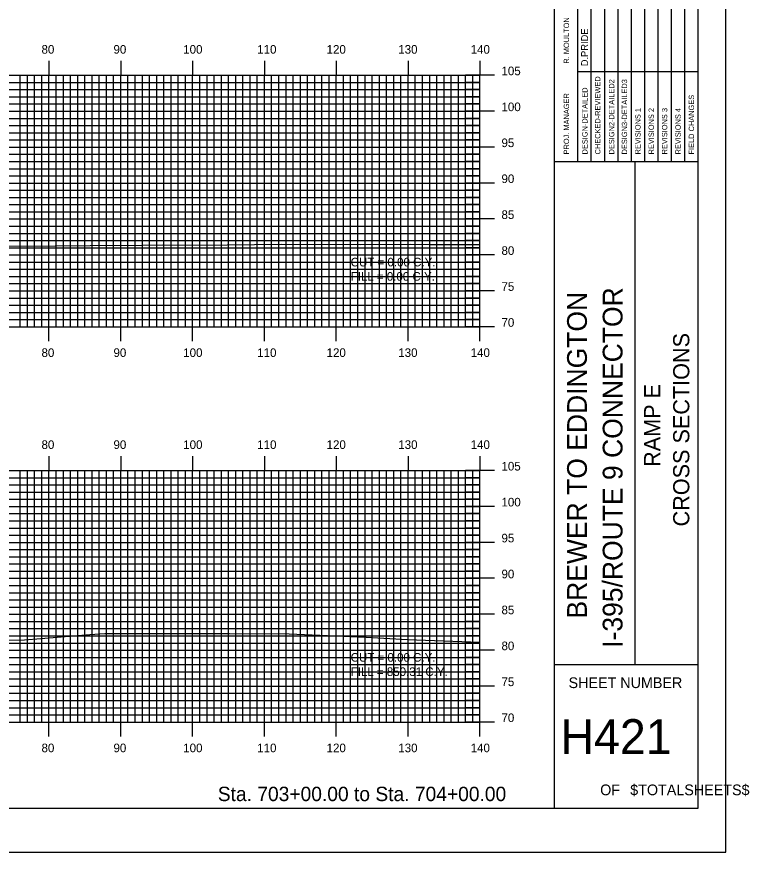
# Model space of a CAD drawing. Extents: x 853329 to 853673, y 364366 to 364586.
# Drawn here: x 853570.7 to 853672.7, y 364365.7 to 364481.9 of the extents above; entities that cross this region are included whole.
import ezdxf

# ---------------------------------------------------------------- set-up
doc = ezdxf.new("R2010")
doc.units = 0
for name, color, linetype in [('BORDER', 7, 'Continuous'), ('D_Text_Standard', 7, 'Continuous'), ('H_V ANNOTATION', 7, 'Continuous'), ('MAJOR', 7, 'Continuous'), ('MINOR', 7, 'Continuous'), ('PLOT BOUNDARY', 7, 'Continuous'), ('S_Roadway_Centerline', 7, 'Continuous')]:
    doc.layers.add(name, color=color, linetype=linetype)

msp = doc.modelspace()

# ---------------------------------------------------------------- linework, layer by layer
at = {"layer": 'BORDER'}
for p, q in [((853645.6, 364371.79), (853645.6, 364581.79)), ((853645.6, 364461.79), (853665.6, 364461.79)), ((853656.79, 364391.79), (853656.79, 364461.79)), ((853645.6, 364391.79), (853665.6, 364391.79))]:
    msp.add_line(p, q, dxfattribs=at)
msp.add_lwpolyline([(853345.6, 364371.79), (853665.6, 364371.79), (853665.6, 364581.79), (853345.6, 364581.79)], close=True, dxfattribs=at)
for points in [[(853650.7, 364461.8), (853650.7, 364496.79)], [(853652.56, 364496.79), (853652.56, 364461.8)], [(853654.43, 364461.8), (853654.43, 364496.79)], [(853656.29, 364461.8), (853656.29, 364496.79)], [(853658.15, 364461.8), (853658.15, 364496.79)], [(853660.02, 364461.8), (853660.02, 364496.79)], [(853661.88, 364461.8), (853661.88, 364496.79)], [(853663.74, 364461.8), (853663.74, 364496.79)], [(853648.84, 364461.8), (853648.84, 364495.38)], [(853648.83, 364474.29), (853665.6, 364474.29)]]:
    msp.add_lwpolyline(points, dxfattribs=at)
at = {"layer": 'MAJOR'}
for p, q in [((853575.2, 364475.79), (853575.2, 364473.79)), ((853585.2, 364475.79), (853585.2, 364473.79)), ((853595.2, 364475.79), (853595.2, 364473.79)), ((853605.2, 364475.79), (853605.2, 364473.79)), ((853615.2, 364475.79), (853615.2, 364473.79)), ((853625.2, 364475.79), (853625.2, 364473.79)), ((853635.2, 364475.79), (853635.2, 364473.79)), ((853355.2, 364473.79), (853635.2, 364473.79)), ((853355.2, 364473.79), (853635.2, 364473.79)), ((853575.2, 364438.79), (853575.2, 364473.79)), ((853585.2, 364438.79), (853585.2, 364473.79)), ((853595.2, 364438.79), (853595.2, 364473.79)), ((853605.2, 364438.79), (853605.2, 364473.79)), ((853615.2, 364438.79), (853615.2, 364473.79)), ((853625.2, 364438.79), (853625.2, 364473.79)), ((853637.21, 364473.79), (853633.2, 364473.79)), ((853635.2, 364438.79), (853635.2, 364473.79)), ((853635.2, 364438.79), (853635.2, 364473.79)), ((853355.2, 364468.79), (853635.2, 364468.79)), ((853637.21, 364468.79), (853633.2, 364468.79)), ((853355.2, 364463.79), (853635.2, 364463.79)), ((853637.21, 364463.79), (853633.2, 364463.79)), ((853355.2, 364458.79), (853635.2, 364458.79)), ((853637.21, 364458.79), (853633.2, 364458.79)), ((853355.2, 364453.79), (853635.2, 364453.79)), ((853637.21, 364453.79), (853633.2, 364453.79)), ((853355.2, 364448.79), (853635.2, 364448.79)), ((853637.21, 364448.79), (853633.2, 364448.79)), ((853355.2, 364443.79), (853635.2, 364443.79)), ((853637.21, 364443.79), (853633.2, 364443.79)), ((853355.2, 364438.79), (853635.2, 364438.79)), ((853355.2, 364438.79), (853635.2, 364438.79)), ((853575.2, 364436.78), (853575.2, 364438.79)), ((853585.2, 364436.78), (853585.2, 364438.79)), ((853595.2, 364436.78), (853595.2, 364438.79)), ((853605.2, 364436.78), (853605.2, 364438.79)), ((853615.2, 364436.78), (853615.2, 364438.79)), ((853625.2, 364436.78), (853625.2, 364438.79)), ((853637.21, 364438.79), (853633.2, 364438.79)), ((853635.2, 364436.78), (853635.2, 364438.79)), ((853575.2, 364420.79), (853575.2, 364418.79)), ((853585.2, 364420.79), (853585.2, 364418.79)), ((853595.2, 364420.79), (853595.2, 364418.79)), ((853605.2, 364420.79), (853605.2, 364418.79)), ((853615.2, 364420.79), (853615.2, 364418.79)), ((853625.2, 364420.79), (853625.2, 364418.79)), ((853635.2, 364420.79), (853635.2, 364418.79)), ((853355.2, 364418.79), (853635.2, 364418.79)), ((853355.2, 364418.79), (853635.2, 364418.79)), ((853575.2, 364383.79), (853575.2, 364418.79)), ((853585.2, 364383.79), (853585.2, 364418.79)), ((853595.2, 364383.79), (853595.2, 364418.79)), ((853605.2, 364383.79), (853605.2, 364418.79)), ((853615.2, 364383.79), (853615.2, 364418.79)), ((853625.2, 364383.79), (853625.2, 364418.79)), ((853637.21, 364418.79), (853633.2, 364418.79)), ((853635.2, 364383.79), (853635.2, 364418.79)), ((853635.2, 364383.79), (853635.2, 364418.79)), ((853355.2, 364413.79), (853635.2, 364413.79)), ((853637.21, 364413.79), (853633.2, 364413.79)), ((853355.2, 364408.79), (853635.2, 364408.79)), ((853637.21, 364408.79), (853633.2, 364408.79)), ((853355.2, 364403.79), (853635.2, 364403.79)), ((853637.21, 364403.79), (853633.2, 364403.79)), ((853355.2, 364398.79), (853635.2, 364398.79)), ((853637.21, 364398.79), (853633.2, 364398.79)), ((853355.2, 364393.79), (853635.2, 364393.79)), ((853637.21, 364393.79), (853633.2, 364393.79)), ((853355.2, 364388.79), (853635.2, 364388.79)), ((853637.21, 364388.79), (853633.2, 364388.79)), ((853355.2, 364383.79), (853635.2, 364383.79)), ((853355.2, 364383.79), (853635.2, 364383.79)), ((853575.2, 364381.78), (853575.2, 364383.79)), ((853585.2, 364381.78), (853585.2, 364383.79)), ((853595.2, 364381.78), (853595.2, 364383.79)), ((853605.2, 364381.78), (853605.2, 364383.79)), ((853615.2, 364381.78), (853615.2, 364383.79)), ((853625.2, 364381.78), (853625.2, 364383.79)), ((853637.21, 364383.79), (853633.2, 364383.79)), ((853635.2, 364381.78), (853635.2, 364383.79))]:
    msp.add_line(p, q, dxfattribs=at)
at = {"layer": 'MINOR'}
for p, q in [((853571.2, 364438.79), (853571.2, 364473.79)), ((853572.2, 364438.79), (853572.2, 364473.79)), ((853573.2, 364438.79), (853573.2, 364473.79)), ((853574.2, 364438.79), (853574.2, 364473.79)), ((853576.2, 364438.79), (853576.2, 364473.79)), ((853577.2, 364438.79), (853577.2, 364473.79)), ((853578.2, 364438.79), (853578.2, 364473.79)), ((853579.2, 364438.79), (853579.2, 364473.79)), ((853580.2, 364438.79), (853580.2, 364473.79)), ((853581.2, 364438.79), (853581.2, 364473.79)), ((853582.2, 364438.79), (853582.2, 364473.79)), ((853583.2, 364438.79), (853583.2, 364473.79)), ((853584.2, 364438.79), (853584.2, 364473.79)), ((853586.2, 364438.79), (853586.2, 364473.79)), ((853587.2, 364438.79), (853587.2, 364473.79)), ((853588.2, 364438.79), (853588.2, 364473.79)), ((853589.2, 364438.79), (853589.2, 364473.79)), ((853590.2, 364438.79), (853590.2, 364473.79)), ((853591.2, 364438.79), (853591.2, 364473.79)), ((853592.2, 364438.79), (853592.2, 364473.79)), ((853593.2, 364438.79), (853593.2, 364473.79)), ((853594.2, 364438.79), (853594.2, 364473.79)), ((853596.2, 364438.79), (853596.2, 364473.79)), ((853597.2, 364438.79), (853597.2, 364473.79)), ((853598.2, 364438.79), (853598.2, 364473.79)), ((853599.2, 364438.79), (853599.2, 364473.79)), ((853600.2, 364438.79), (853600.2, 364473.79)), ((853601.2, 364438.79), (853601.2, 364473.79)), ((853602.2, 364438.79), (853602.2, 364473.79)), ((853603.2, 364438.79), (853603.2, 364473.79)), ((853604.2, 364438.79), (853604.2, 364473.79)), ((853606.2, 364438.79), (853606.2, 364473.79)), ((853607.2, 364438.79), (853607.2, 364473.79)), ((853608.2, 364438.79), (853608.2, 364473.79)), ((853609.2, 364438.79), (853609.2, 364473.79)), ((853610.2, 364438.79), (853610.2, 364473.79)), ((853611.2, 364438.79), (853611.2, 364473.79)), ((853612.2, 364438.79), (853612.2, 364473.79)), ((853613.2, 364438.79), (853613.2, 364473.79)), ((853614.2, 364438.79), (853614.2, 364473.79)), ((853616.2, 364438.79), (853616.2, 364473.79)), ((853617.2, 364438.79), (853617.2, 364473.79)), ((853618.2, 364438.79), (853618.2, 364473.79)), ((853619.2, 364438.79), (853619.2, 364473.79)), ((853620.2, 364438.79), (853620.2, 364473.79)), ((853621.2, 364438.79), (853621.2, 364473.79)), ((853622.2, 364438.79), (853622.2, 364473.79)), ((853623.2, 364438.79), (853623.2, 364473.79)), ((853624.2, 364438.79), (853624.2, 364473.79)), ((853626.2, 364438.79), (853626.2, 364473.79)), ((853627.2, 364438.79), (853627.2, 364473.79)), ((853628.2, 364438.79), (853628.2, 364473.79)), ((853629.2, 364438.79), (853629.2, 364473.79)), ((853630.2, 364438.79), (853630.2, 364473.79)), ((853631.2, 364438.79), (853631.2, 364473.79)), ((853632.2, 364438.79), (853632.2, 364473.79)), ((853633.2, 364438.79), (853633.2, 364473.79)), ((853634.2, 364438.79), (853634.2, 364473.79)), ((853355.2, 364472.79), (853635.2, 364472.79)), ((853635.2, 364472.79), (853633.2, 364472.79)), ((853355.2, 364471.79), (853635.2, 364471.79)), ((853355.2, 364470.79), (853635.2, 364470.79)), ((853635.2, 364471.79), (853633.2, 364471.79)), ((853635.2, 364470.79), (853633.2, 364470.79)), ((853355.2, 364469.79), (853635.2, 364469.79)), ((853635.2, 364469.79), (853633.2, 364469.79)), ((853355.2, 364467.79), (853635.2, 364467.79)), ((853635.2, 364467.79), (853633.2, 364467.79)), ((853355.2, 364466.79), (853635.2, 364466.79)), ((853635.2, 364466.79), (853633.2, 364466.79)), ((853355.2, 364465.79), (853635.2, 364465.79)), ((853635.2, 364465.79), (853633.2, 364465.79)), ((853355.2, 364464.79), (853635.2, 364464.79)), ((853635.2, 364464.79), (853633.2, 364464.79)), ((853355.2, 364462.79), (853635.2, 364462.79)), ((853635.2, 364462.79), (853633.2, 364462.79)), ((853355.2, 364461.79), (853635.2, 364461.79)), ((853635.2, 364461.79), (853633.2, 364461.79)), ((853355.2, 364460.79), (853635.2, 364460.79)), ((853635.2, 364460.79), (853633.2, 364460.79)), ((853355.2, 364459.79), (853635.2, 364459.79)), ((853635.2, 364459.79), (853633.2, 364459.79)), ((853355.2, 364457.79), (853635.2, 364457.79)), ((853355.2, 364456.79), (853635.2, 364456.79)), ((853635.2, 364457.79), (853633.2, 364457.79)), ((853635.2, 364456.79), (853633.2, 364456.79)), ((853355.2, 364455.79), (853635.2, 364455.79)), ((853635.2, 364455.79), (853633.2, 364455.79)), ((853355.2, 364454.79), (853635.2, 364454.79)), ((853635.2, 364454.79), (853633.2, 364454.79)), ((853355.2, 364452.79), (853635.2, 364452.79)), ((853635.2, 364452.79), (853633.2, 364452.79)), ((853355.2, 364451.79), (853635.2, 364451.79)), ((853635.2, 364451.79), (853633.2, 364451.79)), ((853355.2, 364450.79), (853635.2, 364450.79)), ((853355.2, 364449.79), (853635.2, 364449.79)), ((853635.2, 364450.79), (853633.2, 364450.79)), ((853635.2, 364449.79), (853633.2, 364449.79)), ((853355.2, 364447.79), (853635.2, 364447.79)), ((853635.2, 364447.79), (853633.2, 364447.79)), ((853355.2, 364446.79), (853635.2, 364446.79)), ((853635.2, 364446.79), (853633.2, 364446.79)), ((853355.2, 364445.79), (853635.2, 364445.79)), ((853635.2, 364445.79), (853633.2, 364445.79)), ((853355.2, 364444.79), (853635.2, 364444.79)), ((853635.2, 364444.79), (853633.2, 364444.79)), ((853355.2, 364442.79), (853635.2, 364442.79)), ((853635.2, 364442.79), (853633.2, 364442.79)), ((853355.2, 364441.79), (853635.2, 364441.79)), ((853635.2, 364441.79), (853633.2, 364441.79)), ((853355.2, 364440.79), (853635.2, 364440.79)), ((853635.2, 364440.79), (853633.2, 364440.79)), ((853355.2, 364439.79), (853635.2, 364439.79)), ((853635.2, 364439.79), (853633.2, 364439.79)), ((853571.2, 364383.79), (853571.2, 364418.79)), ((853572.2, 364383.79), (853572.2, 364418.79)), ((853573.2, 364383.79), (853573.2, 364418.79)), ((853574.2, 364383.79), (853574.2, 364418.79)), ((853576.2, 364383.79), (853576.2, 364418.79)), ((853577.2, 364383.79), (853577.2, 364418.79)), ((853578.2, 364383.79), (853578.2, 364418.79)), ((853579.2, 364383.79), (853579.2, 364418.79)), ((853580.2, 364383.79), (853580.2, 364418.79)), ((853581.2, 364383.79), (853581.2, 364418.79)), ((853582.2, 364383.79), (853582.2, 364418.79)), ((853583.2, 364383.79), (853583.2, 364418.79)), ((853584.2, 364383.79), (853584.2, 364418.79)), ((853586.2, 364383.79), (853586.2, 364418.79)), ((853587.2, 364383.79), (853587.2, 364418.79)), ((853588.2, 364383.79), (853588.2, 364418.79)), ((853589.2, 364383.79), (853589.2, 364418.79)), ((853590.2, 364383.79), (853590.2, 364418.79)), ((853591.2, 364383.79), (853591.2, 364418.79)), ((853592.2, 364383.79), (853592.2, 364418.79)), ((853593.2, 364383.79), (853593.2, 364418.79)), ((853594.2, 364383.79), (853594.2, 364418.79)), ((853596.2, 364383.79), (853596.2, 364418.79)), ((853597.2, 364383.79), (853597.2, 364418.79)), ((853598.2, 364383.79), (853598.2, 364418.79)), ((853599.2, 364383.79), (853599.2, 364418.79)), ((853600.2, 364383.79), (853600.2, 364418.79)), ((853601.2, 364383.79), (853601.2, 364418.79)), ((853602.2, 364383.79), (853602.2, 364418.79)), ((853603.2, 364383.79), (853603.2, 364418.79)), ((853604.2, 364383.79), (853604.2, 364418.79)), ((853606.2, 364383.79), (853606.2, 364418.79)), ((853607.2, 364383.79), (853607.2, 364418.79)), ((853608.2, 364383.79), (853608.2, 364418.79)), ((853609.2, 364383.79), (853609.2, 364418.79)), ((853610.2, 364383.79), (853610.2, 364418.79)), ((853611.2, 364383.79), (853611.2, 364418.79)), ((853612.2, 364383.79), (853612.2, 364418.79)), ((853613.2, 364383.79), (853613.2, 364418.79)), ((853614.2, 364383.79), (853614.2, 364418.79)), ((853616.2, 364383.79), (853616.2, 364418.79)), ((853617.2, 364383.79), (853617.2, 364418.79)), ((853618.2, 364383.79), (853618.2, 364418.79)), ((853619.2, 364383.79), (853619.2, 364418.79)), ((853620.2, 364383.79), (853620.2, 364418.79)), ((853621.2, 364383.79), (853621.2, 364418.79)), ((853622.2, 364383.79), (853622.2, 364418.79)), ((853623.2, 364383.79), (853623.2, 364418.79)), ((853624.2, 364383.79), (853624.2, 364418.79)), ((853626.2, 364383.79), (853626.2, 364418.79)), ((853627.2, 364383.79), (853627.2, 364418.79)), ((853628.2, 364383.79), (853628.2, 364418.79)), ((853629.2, 364383.79), (853629.2, 364418.79)), ((853630.2, 364383.79), (853630.2, 364418.79)), ((853631.2, 364383.79), (853631.2, 364418.79)), ((853632.2, 364383.79), (853632.2, 364418.79)), ((853633.2, 364383.79), (853633.2, 364418.79)), ((853634.2, 364383.79), (853634.2, 364418.79)), ((853355.2, 364417.79), (853635.2, 364417.79)), ((853635.2, 364417.79), (853633.2, 364417.79)), ((853355.2, 364416.79), (853635.2, 364416.79)), ((853635.2, 364416.79), (853633.2, 364416.79)), ((853355.2, 364415.79), (853635.2, 364415.79)), ((853635.2, 364415.79), (853633.2, 364415.79)), ((853355.2, 364414.79), (853635.2, 364414.79)), ((853635.2, 364414.79), (853633.2, 364414.79)), ((853355.2, 364412.79), (853635.2, 364412.79)), ((853635.2, 364412.79), (853633.2, 364412.79)), ((853355.2, 364411.79), (853635.2, 364411.79)), ((853635.2, 364411.79), (853633.2, 364411.79)), ((853355.2, 364410.79), (853635.2, 364410.79)), ((853635.2, 364410.79), (853633.2, 364410.79)), ((853355.2, 364409.79), (853635.2, 364409.79)), ((853635.2, 364409.79), (853633.2, 364409.79)), ((853355.2, 364407.79), (853635.2, 364407.79)), ((853355.2, 364406.79), (853635.2, 364406.79)), ((853635.2, 364407.79), (853633.2, 364407.79)), ((853635.2, 364406.79), (853633.2, 364406.79)), ((853355.2, 364405.79), (853635.2, 364405.79)), ((853635.2, 364405.79), (853633.2, 364405.79)), ((853355.2, 364404.79), (853635.2, 364404.79)), ((853635.2, 364404.79), (853633.2, 364404.79)), ((853355.2, 364402.79), (853635.2, 364402.79)), ((853635.2, 364402.79), (853633.2, 364402.79)), ((853355.2, 364401.79), (853635.2, 364401.79)), ((853635.2, 364401.79), (853633.2, 364401.79)), ((853355.2, 364400.79), (853635.2, 364400.79)), ((853355.2, 364399.79), (853635.2, 364399.79)), ((853635.2, 364400.79), (853633.2, 364400.79)), ((853635.2, 364399.79), (853633.2, 364399.79)), ((853355.2, 364397.79), (853635.2, 364397.79)), ((853635.2, 364397.79), (853633.2, 364397.79)), ((853355.2, 364396.79), (853635.2, 364396.79)), ((853635.2, 364396.79), (853633.2, 364396.79)), ((853355.2, 364395.79), (853635.2, 364395.79)), ((853635.2, 364395.79), (853633.2, 364395.79)), ((853355.2, 364394.79), (853635.2, 364394.79)), ((853635.2, 364394.79), (853633.2, 364394.79)), ((853355.2, 364392.79), (853635.2, 364392.79)), ((853355.2, 364391.79), (853635.2, 364391.79)), ((853635.2, 364392.79), (853633.2, 364392.79)), ((853635.2, 364391.79), (853633.2, 364391.79)), ((853355.2, 364390.79), (853635.2, 364390.79)), ((853635.2, 364390.79), (853633.2, 364390.79)), ((853355.2, 364389.79), (853635.2, 364389.79)), ((853635.2, 364389.79), (853633.2, 364389.79)), ((853355.2, 364387.79), (853635.2, 364387.79)), ((853635.2, 364387.79), (853633.2, 364387.79)), ((853355.2, 364386.79), (853635.2, 364386.79)), ((853635.2, 364386.79), (853633.2, 364386.79)), ((853355.2, 364385.79), (853635.2, 364385.79)), ((853355.2, 364384.79), (853635.2, 364384.79)), ((853635.2, 364385.79), (853633.2, 364385.79)), ((853635.2, 364384.79), (853633.2, 364384.79))]:
    msp.add_line(p, q, dxfattribs=at)
at = {"layer": 'PLOT BOUNDARY'}
msp.add_lwpolyline([(853329.42, 364365.67), (853669.42, 364365.67), (853669.42, 364585.67), (853329.42, 364585.67)], close=True, dxfattribs=at)
at = {"layer": 'S_Roadway_Centerline'}
for points in [[(853567.94, 364450.11), (853571.2, 364450.03), (853580.94, 364450.09), (853588.26, 364450.13), (853591.04, 364450.17), (853596.25, 364450.15), (853607.56, 364450.27), (853618.59, 364450.24), (853625.54, 364450.29), (853628.12, 364450.26), (853632.93, 364450.23), (853635.2, 364450.23)], [(853461.87, 364393.67), (853472.58, 364394.44), (853474.39, 364394.4), (853493.12, 364394.47), (853507.75, 364394.63), (853510.68, 364394.6), (853513.41, 364394.63), (853526.99, 364394.71), (853541.49, 364395), (853546.8, 364395.05), (853549.27, 364395.15), (853559.15, 364395.19), (853564.15, 364395.13), (853571.8, 364395.22), (853580.87, 364395.97), (853582.99, 364396.12), (853600.33, 364396.12), (853608.66, 364396.07), (853619.34, 364395.61), (853625.11, 364395.29), (853635.2, 364394.92)]]:
    msp.add_lwpolyline(points, dxfattribs=at)

# ---------------------------------------------------------------- texts
at = {"layer": 'BORDER'}
for s, height, p in [('R. MOULTON', 0.745, (853647.61, 364475.4)), ('D.PRIDE', 0.969, (853650.25, 364475.04)), ('CHECKED-REVIEWED', 0.7455, (853651.97, 364462.77)), ('DESIGN2-DETAILED2', 0.7455, (853653.9, 364462.77)), ('DESIGN3-DETAILED3', 0.7455, (853655.69, 364462.77)), ('PROJ. MANAGER', 0.7455, (853647.61, 364462.77)), ('DESIGN-DETAILED', 0.7455, (853650.18, 364462.77)), ('FIELD CHANGES', 0.7455, (853665.01, 364462.77)), ('REVISIONS 1', 0.7455, (853657.56, 364462.77)), ('REVISIONS 2', 0.7455, (853659.42, 364462.77)), ('REVISIONS 3', 0.7455, (853661.28, 364462.77)), ('REVISIONS 4', 0.7455, (853663.15, 364462.77)), ('I-395/ROUTE 9 CONNECTOR', 2.7557, (853655.05, 364394.12)), ('BREWER TO EDDINGTON', 2.7557, (853650.09, 364398.2)), ('CROSS SECTIONS', 2.25, (853664.35, 364411.01)), ('RAMP E', 2.25, (853660.3, 364419.29))]:
    msp.add_text(s, height=height, rotation=90, dxfattribs=at).set_placement(p)
for s, height, p in [('SHEET NUMBER', 1.4905, (853647.54, 364388.52)), ('H421', 4.839, (853646.41, 364379.35)), ('OF', 1.491, (853651.94, 364373.61)), ('$TOTALSHEETS$', 1.4905, (853656.12, 364373.61))]:
    msp.add_text(s, height=height, dxfattribs=at).set_placement(p)
at = {"layer": 'D_Text_Standard'}
for s, p in [('CUT = 0.00 C.Y.', (853617.2, 364447.19)), ('FILL = 0.00 C.Y.', (853617.2, 364445.2)), ('CUT = 0.00 C.Y.', (853617.2, 364392.19)), ('FILL = 850.31 C.Y.', (853617.2, 364390.2))]:
    msp.add_text(s, height=1.2, dxfattribs=at).set_placement(p)
at = {"layer": 'H_V ANNOTATION'}
for s, height, p in [('80', 1.2, (853574.16, 364476.79)), ('90', 1.2, (853584.18, 364476.79)), ('100', 1.2, (853593.89, 364476.79)), ('110', 1.2, (853604.19, 364476.79)), ('120', 1.2, (853613.85, 364476.79)), ('130', 1.2, (853623.83, 364476.79)), ('140', 1.2, (853633.91, 364476.79)), ('105', 1.2, (853638.2, 364473.79)), ('100', 1.2, (853638.2, 364468.79)), ('95', 1.2, (853638.2, 364463.79)), ('90', 1.2, (853638.2, 364458.79)), ('85', 1.2, (853638.2, 364453.79)), ('80', 1.2, (853638.2, 364448.79)), ('75', 1.2, (853638.2, 364443.79)), ('70', 1.2, (853638.2, 364438.79)), ('80', 1.2, (853574.16, 364434.59)), ('90', 1.2, (853584.18, 364434.59)), ('100', 1.2, (853593.89, 364434.59)), ('110', 1.2, (853604.19, 364434.59)), ('120', 1.2, (853613.85, 364434.59)), ('130', 1.2, (853623.83, 364434.59)), ('140', 1.2, (853633.91, 364434.59)), ('80', 1.2, (853574.16, 364421.79)), ('90', 1.2, (853584.18, 364421.79)), ('100', 1.2, (853593.89, 364421.79)), ('110', 1.2, (853604.19, 364421.79)), ('120', 1.2, (853613.85, 364421.79)), ('130', 1.2, (853623.83, 364421.79)), ('140', 1.2, (853633.91, 364421.79)), ('105', 1.2, (853638.2, 364418.79)), ('100', 1.2, (853638.2, 364413.79)), ('95', 1.2, (853638.2, 364408.79)), ('90', 1.2, (853638.2, 364403.79)), ('85', 1.2, (853638.2, 364398.79)), ('80', 1.2, (853638.2, 364393.79)), ('75', 1.2, (853638.2, 364388.79)), ('70', 1.2, (853638.2, 364383.79)), ('80', 1.2, (853574.16, 364379.59)), ('90', 1.2, (853584.18, 364379.59)), ('100', 1.2, (853593.89, 364379.59)), ('110', 1.2, (853604.19, 364379.59)), ('120', 1.2, (853613.85, 364379.59)), ('130', 1.2, (853623.83, 364379.59)), ('140', 1.2, (853633.91, 364379.59)), ('Sta. 703+00.00 to Sta. 704+00.00', 2.0004, (853598.7, 364372.79))]:
    msp.add_text(s, height=height, dxfattribs=at).set_placement(p)

doc.saveas('drawing.dxf')
